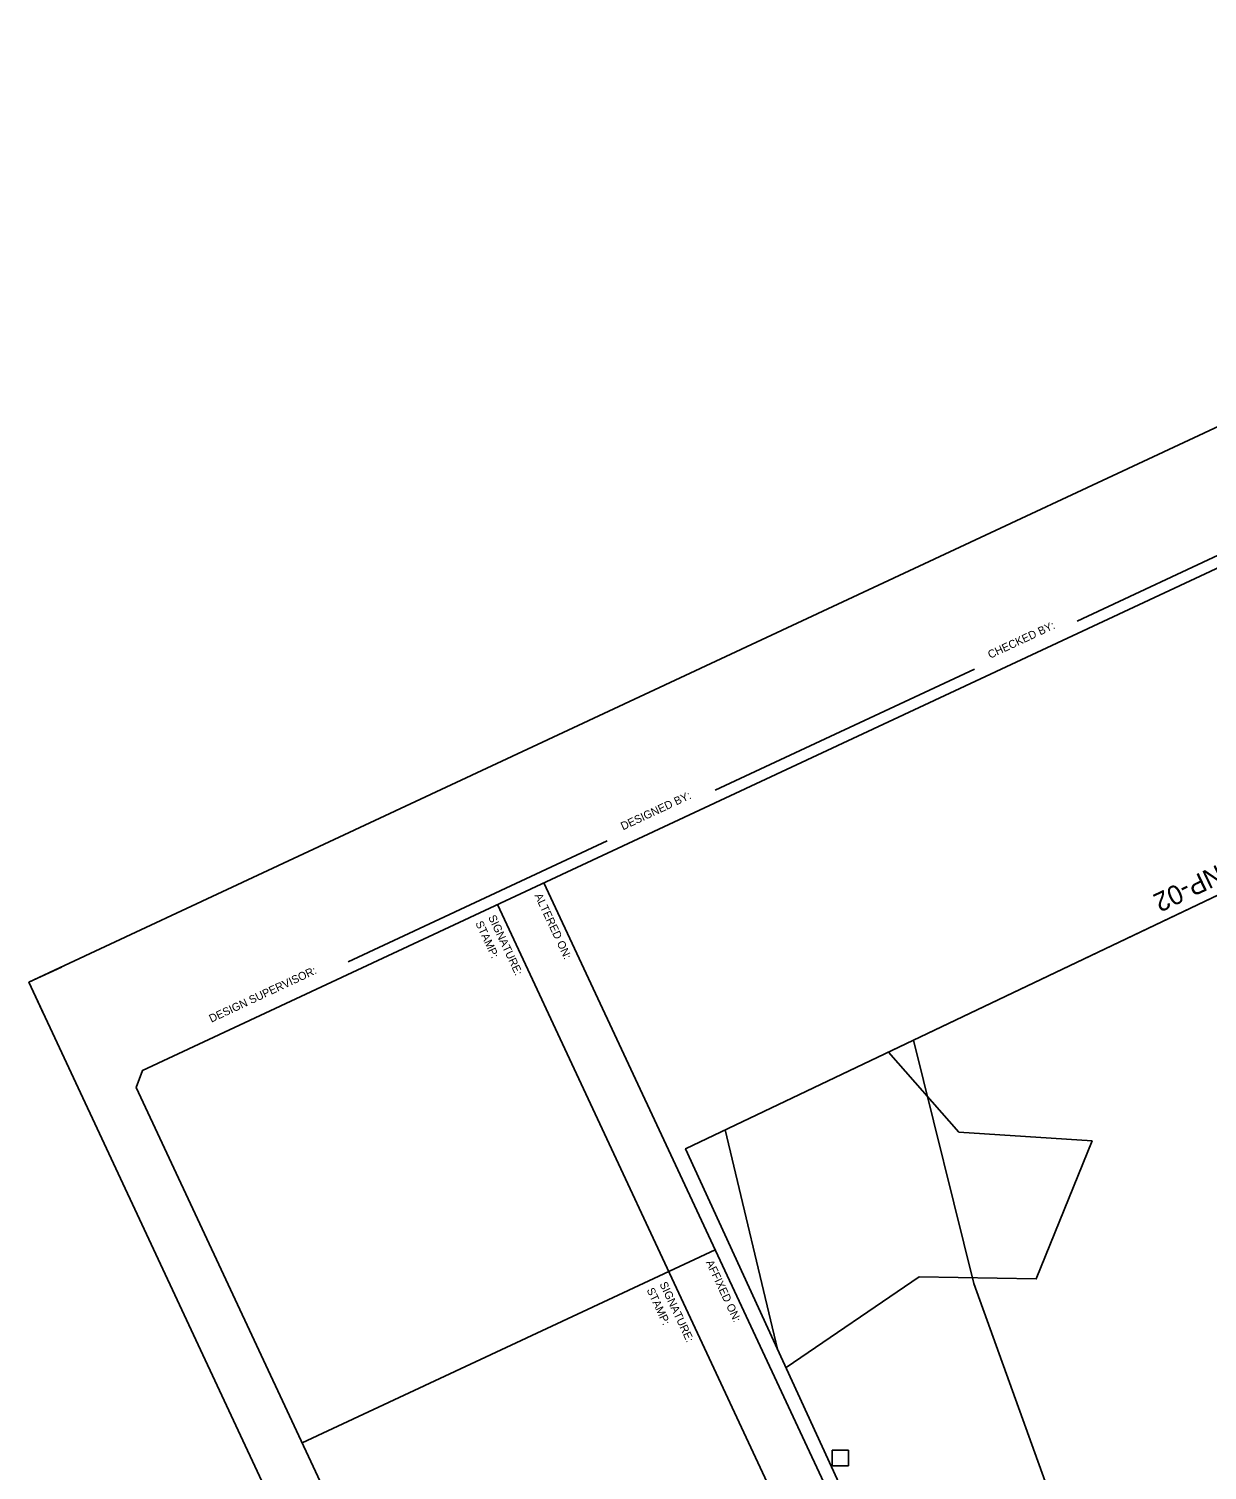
# Model space of a CAD drawing. Extents: x 1040567 to 1041254, y 1126791 to 1127594.
# Drawn here: x 1040567.2 to 1040797.5, y 1127312.2 to 1127593.6 of the extents above; entities that cross this region are included whole.
import ezdxf

# ---------------------------------------------------------------- set-up
doc = ezdxf.new("R2010")
doc.units = 0
for name, color, linetype in [('clip boundary', 7, 'Continuous'), ('LAWA', 7, 'Continuous'), ('LELB', 7, 'Continuous'), ('MHB', 7, 'Continuous'), ('MPM', 7, 'Continuous'), ('NML_P', 7, 'Continuous'), ('NML_P_T', 7, 'Continuous'), ('SHEET_BORDER', 7, 'Continuous'), ('SHEET_BORDER_CUT', 7, 'Continuous'), ('SHEET_BORDER_STAMPBOX', 7, 'Continuous'), ('SHEET_BORDER_TEXT', 7, 'Continuous')]:
    doc.layers.add(name, color=color, linetype=linetype)

msp = doc.modelspace()

# ---------------------------------------------------------------- linework, layer by layer
at = {"layer": 'clip boundary'}
for points in [[(1040965.89, 1127593.65), (1041253.68, 1126977.55), (1040855.03, 1126791.33), (1040567.24, 1127407.43)], [(1040984.84, 1127512.73), (1041214.88, 1127013.05), (1040933.62, 1126879.17), (1040829.04, 1127018.95), (1040710.75, 1127268.88), (1040738.34, 1127281.77), (1040695.57, 1127374.92)]]:
    msp.add_lwpolyline(points, close=True, dxfattribs=at)
at = {"layer": 'LAWA'}
msp.add_lwpolyline([(1040735.21, 1127393.81), (1040748.95, 1127378.16), (1040774.99, 1127376.47), (1040764.08, 1127349.5), (1040741.19, 1127349.88), (1040715.19, 1127332.2)], dxfattribs=at)
at = {"layer": 'LELB'}
msp.add_lwpolyline([(1040766.38, 1127308.3), (1040751.85, 1127348.64), (1040740.09, 1127396.13)], dxfattribs=at)
at = {"layer": 'MHB'}
msp.add_lwpolyline([(1040713.53, 1127335.81), (1040703.31, 1127378.61)], dxfattribs=at)
at = {"layer": 'MPM'}
for p, q in [((1040724.2, 1127313.03), (1040724.2, 1127316.09)), ((1040724.2, 1127316.09), (1040727.36, 1127316.09)), ((1040727.36, 1127316.09), (1040727.36, 1127313.03)), ((1040727.36, 1127313.03), (1040724.2, 1127313.03))]:
    msp.add_line(p, q, dxfattribs=at)
at = {"layer": 'NML_P'}
msp.add_line((1040710.81, 1127382.18), (1040984.84, 1127512.73), dxfattribs=at)
at = {"layer": 'SHEET_BORDER'}
for p, q in [((1040772.08, 1127477.98), (1040822.74, 1127501.65)), ((1040701.36, 1127444.95), (1040752.02, 1127468.61)), ((1040629.63, 1127411.44), (1040680.23, 1127435.08))]:
    msp.add_line(p, q, dxfattribs=at)
msp.add_lwpolyline([(1040856.06, 1126819.41), (1040852.74, 1126820.61), (1040588.22, 1127386.88), (1040589.43, 1127390.2), (1040964.86, 1127565.58), (1040968.18, 1127564.37), (1041232.7, 1126998.11), (1041231.49, 1126994.78)], close=True, dxfattribs=at)
at = {"layer": 'SHEET_BORDER_CUT'}
msp.add_lwpolyline([(1040567.24, 1127407.43), (1040855.03, 1126791.33), (1041253.68, 1126977.55), (1040965.89, 1127593.65)], close=True, dxfattribs=at)
msp.add_lwpolyline([(1040570.23, 1127401.02), (1040567.24, 1127407.43), (1040573.64, 1127410.42)], dxfattribs=at)
at = {"layer": 'SHEET_BORDER_STAMPBOX'}
for p, q in [((1040667.85, 1127426.84), (1040734.78, 1127283.57)), ((1040725.72, 1127279.34), (1040658.79, 1127422.6)), ((1040620.62, 1127317.51), (1040701.31, 1127355.2))]:
    msp.add_line(p, q, dxfattribs=at)

# ---------------------------------------------------------------- texts
at = {"layer": 'NML_P_T'}
msp.add_text('MATCHLINE STA. 7+50 - SEE DWG. GNP-02', height=3.744, rotation=205.4736, dxfattribs=at).set_placement((1040879.68, 1127468.73))
at = {"layer": 'SHEET_BORDER_STAMPBOX'}
for s, height, p in [('ALTERED ON:', 1.5625, (1040666.02, 1127424.39)), ('STAMP:', 1.562, (1040654.45, 1127418.98)), ('SIGNATURE:', 1.562, (1040656.96, 1127420.16)), ('AFFIXED ON:', 1.5625, (1040699.48, 1127352.76)), ('SIGNATURE:', 1.562, (1040690.42, 1127348.52)), ('STAMP:', 1.562, (1040687.91, 1127347.35))]:
    msp.add_text(s, height=height, rotation=295.0387, dxfattribs=at).set_placement(p)
at = {"layer": 'SHEET_BORDER_TEXT'}
for s, p in [('CHECKED BY:', (1040755.06, 1127470.61)), ('DESIGNED BY:', (1040683.33, 1127437.1)), ('DESIGN SUPERVISOR:', (1040602.9, 1127399.53))]:
    msp.add_text(s, height=1.5625, rotation=25.0387, dxfattribs=at).set_placement(p)

doc.saveas('drawing.dxf')
